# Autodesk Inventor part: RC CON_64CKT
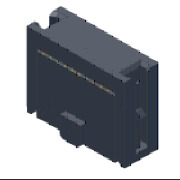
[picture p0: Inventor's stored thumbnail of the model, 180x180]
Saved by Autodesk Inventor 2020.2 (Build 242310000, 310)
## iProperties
Manager: www.cadconsulting.pl
Company: Fabian Stasiak CAD Consulting
IsCustomPart: 0
Created: 2014-02
Part Number: RC CON_64CKT
Material: Ogólny
Description: Podziałka 2.54mm (0.10cala), gniazdo, pionowe, dwurzędowe
Document SubType Name: Modeling
Designer: F.Stasiak
Language: pl-PL
Size Designation: Ribbon Cable Connector-13
Categories: <MemberInstance><Categories><Category DisplayName="Kable i wiązki przewodów" InternalName="e4a7e005-5e42-4d16-b293-125e7f0d0512" Mnemonic="CABLEANDHARNESS"><Cat
Density: 1 g/cm^3
Appearance: Dark Gray
Catalog Web Link: www.expertbooks.pl
Author: F.Stasiak
Subject: Zbiór ćwiczeń. Autodesk Inventor 2020. Kurs Professional
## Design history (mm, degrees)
sketch "Sketch1"
  geometry: L1 (41.27, -3)-(-41.27, -3); L2 (-40.52, -1.5)-(-40.52, -2.1); L3 (-41.27, -3)-(-41.27, -2.1); L4 (-40.52, -2.1)-(-41.27, -2.1); L5 (-41.27, -1.5)-(-40.52, -1.5); L6 (-41.27, -1.5)-(-41.27, 3); L7 (40.52, 1.5)-(40.52, 2.1); L8 (41.27, 1.5)-(41.27, -3); L9 (41.27, 1.5)-(40.52, 1.5); L10 (40.52, 2.1)-(41.27, 2.1); L11 (41.27, 3)-(41.27, 2.1); L12 (0, 3)-(0, -3); L13 (-41.27, 3)-(41.27, 3); 2 further points
  constraints: 26 end point, 8 parallel, 3 midpoint, 3 perpendicular, 2 horizontal, 1 coincident
  dimensions: "d0" = 82.54 distance of L1.start L1.end (derived); "d1" = 6 distance of L1.end L6.end; "d4" = 0.9 distance between parallel lines of L1 L4; "d5" = 0.75 distance of L2.end L3.end; "d6" = 0.6 distance of L2.start L2.end; "d8" = 0.75 distance of L7.end L10.end; "d9" = 0.6 distance of L7.start L7.end; "d10" = 6 distance of L1.start L11.start; "d12" = 0.9 distance of L11.start L10.end
extrude "Wyciągnięcie1" new body sketch "Sketch1" distance "d13" = 10.2; taper "d14" = 0 deg
sketch "Sketch2"
  geometry: L1 (0, 0)-(82.54, 0) reference; L2 (39.47, 3.6)-(43.07, 3.6); L3 (43.07, 3.6)-(43.07, 0.5); L4 (42.57, 0)-(39.97, 0); L5 (39.47, 0.5)-(39.47, 3.6); L6 (39.47, 0.5)-(39.97, 0); L7 (43.07, 0.5)-(42.57, 0); 1 further point
  constraints: 12 end point, 2 midpoint, 2 parallel, 1 horizontal, 1 perpendicular
  dimensions: "d15" = 3.6 distance of L2.start L2.end; "d17" = 0.5 horizontal distance of L4.end L5.start; "d19" = 135 deg angle of L6 L5; "d20" = 135 deg angle of L7 L3; "d21" = 0.5 horizontal distance of L4.start L3.end; "d22" = 3.6 distance between parallel lines of L1 L2
extrude "Wyciągnięcie2" join sketch "Sketch2" distance "d23" = 1; taper "d24" = 0 deg
sketch "Sketch3"
  geometry: L1 (-41.27, 3.6)-(-41.52, 3.6); L2 (-42.27, 2.1)-(-42.27, 1.22); L3 (-42.27, 1.22)-(-41.27, 1.22); L4 (-41.27, 1.22)-(-41.27, 3.6); L5 (41.27, 10.2)-(-41.27, 10.2) reference; L6 (0, 10.2)-(0, 0); L7 (-41.27, 0)-(41.27, 0) reference; L8 (-41.52, 3.6)-(-42.27, 2.1); L9 (41.27, 3.6)-(41.52, 3.6); L10 (42.27, 2.1)-(42.27, 1.22); L11 (42.27, 1.22)-(41.27, 1.22); L12 (41.27, 1.22)-(41.27, 3.6); L13 (41.52, 3.6)-(42.27, 2.1)
  constraints: 22 end point, 5 symmetric about line, 2 midpoint, 2 parallel, 2 perpendicular, 1 horizontal
  dimensions: "d25" = 82.54 diameter of L4 L6 (derived); "d26" = 1.22 distance between parallel lines of L3 L7; "d28" = 1 distance of L2.end L3.end; "d29" = 1.5 vertical distance of L1.end L2.start; "d30" = 0.88 distance of L2.start L2.end; "d31" = 0.25 distance of L1.start L1.end
extrude "Wyciągnięcie3" join sketch "Sketch3" stored distance "d32" = 1; taper "d33" = 0 deg
sketch "Sketch4"
  geometry: L1 (41.27, 3.6)-(41.52, 3.6) reference; L2 (41.27, 6.263)-(41.52, 6.263); L3 (42.27, 5.513)-(42.27, 5.263); L4 (42.27, 5.263)-(41.27, 5.263); L5 (41.27, 5.263)-(41.27, 6.263); L6 (-41.27, 10.2)-(41.27, 10.2) reference; L7 (41.27, 0)-(-41.27, 0) reference; L8 (0, 10.2)-(0, 0); L9 (41.52, 6.263)-(42.27, 5.513); L10 (-41.27, 5.263)-(-41.27, 6.263); L11 (-41.27, 6.263)-(-41.52, 6.263); L12 (-41.52, 6.263)-(-42.27, 5.513); L13 (-42.27, 5.513)-(-42.27, 5.263); L14 (-42.27, 5.263)-(-41.27, 5.263)
  constraints: 22 end point, 5 symmetric about line, 2 midpoint, 2 parallel, 1 horizontal, 1 perpendicular
  dimensions: "d34" = 1.663 distance between parallel lines of L4 L1; "d35" = 82.54 diameter of L5 L8 (derived); "d36" = 1 distance of L3.end L4.end; "d38" = 0.25 distance of L2.start L2.end; "d39" = 1 distance of L4.end L2.start; "d40" = 0.25 distance of L3.start L3.end
extrude "Wyciągnięcie4" join sketch "Sketch4" distance "d41" = 1; taper "d42" = 0 deg
sketch "Sketch5"
  geometry: L1 (41.52, -3.6)-(41.27, -3.6) reference; L2 (41.52, -6.263)-(41.27, -6.263); L3 (41.27, -6.263)-(41.27, -5.263); L4 (41.27, -5.263)-(42.27, -5.263); L5 (42.27, -5.263)-(42.27, -5.513); L6 (41.27, -10.2)-(-41.27, -10.2) reference; L7 (1.3, 0)-(-1.3, 0) reference; L8 (0, 0)-(0, -10.2); L9 (41.52, -6.263)-(42.27, -5.513); L10 (-41.27, -6.263)-(-41.27, -5.263); L11 (-41.52, -6.263)-(-41.27, -6.263); L12 (-41.52, -6.263)-(-42.27, -5.513); L13 (-42.27, -5.263)-(-42.27, -5.513); L14 (-41.27, -5.263)-(-42.27, -5.263)
  constraints: 22 end point, 5 symmetric about line, 2 midpoint, 2 parallel, 1 horizontal, 1 perpendicular
  dimensions: "d43" = 1.663 distance between parallel lines of L1 L4; "d44" = 82.54 diameter of L3 L8 (derived); "d45" = 1 distance of L2.end L3.end; "d46" = 1 distance of L3.end L4.end; "d47" = 0.25 distance of L2.start L2.end; "d48" = 0.25 distance of L4.end L5.end
extrude "Wyciągnięcie5" join sketch "Sketch5" distance "d49" = 1; taper "d50" = 0 deg
sketch "Sketch6"
  geometry: L1 (0, -10.2)-(39.97, -10.2) reference; L2 (-36.97, -6.736)-(-34.97, -10.2); L3 (-38.97, -10.2)-(-36.97, -6.736); L4 (-38.97, -10.2)-(-34.97, -10.2); L5 (0.5, -10.2)-(2.5, -6.736); L6 (2.5, -6.736)-(4.5, -10.2); L7 (0.5, -10.2)-(4.5, -10.2)
  constraints: 12 end point, 4 equal length, 2 point on line, 1 collinear
  dimensions: "d61" = 0.5 distance of L5.start L1.start; "d62" = 4 distance of L5.start L6.end
extrude "Wyciągnięcie6" cut sketch "Sketch6" distance "d63" = 0.1; taper "d64" = 0 deg
sketch "Sketch7"
  geometry: L1 (41.27, 3)-(41.27, -1.5) reference; L2 (38.995, 1.645)-(39.745, 1.645); L3 (39.745, 1.645)-(39.745, 0.895); L4 (39.745, 0.895)-(38.995, 0.895); L5 (38.995, 0.895)-(38.995, 1.645); L6 (38.995, -0.895)-(39.745, -0.895); L7 (39.745, -0.895)-(39.745, -1.645); L8 (39.745, -1.645)-(38.995, -1.645); L9 (38.995, -1.645)-(38.995, -0.895); L10 (39.37, 0.895)-(39.37, -0.895); 2 further points
  constraints: 18 end point, 7 equal length, 4 parallel, 3 midpoint, 3 perpendicular, 2 horizontal, 1 horizontal alignment
  dimensions: "d65" = 0.75 distance of L2.start L2.end; "d66" = 2.54 distance between parallel lines of L6 L2; "d67" = 1.525 distance between parallel lines of L1 L7
extrude "Wyciągnięcie7" cut sketch "Sketch7" distance "d68" = 3; taper "d69" = 0 deg
workplane "Work Plane1"
sketch "Sketch8"
  geometry: L1 (-42.251, -1.499)-(-41.4, -1.499); L2 (-42.955, -1.03)-(-42.251, -1.499); L3 (-42.955, -3.03)-(-42.955, -1.03); L4 (42.955, -3.03)-(-42.955, -3.03); L5 (-42.955, 3.03)-(42.955, 3.03); L6 (-41.4, -1.499)-(-41.4, 1.499); L7 (-41.27, 3)-(41.27, 3) reference; L8 (-41.27, -1.5)-(-41.27, 3) reference; L9 (-40.52, -1.5)-(-41.27, -1.5) reference; L10 (-40.52, -2.1)-(-40.52, -1.5) reference; L11 (-41.27, -2.1)-(-40.52, -2.1) reference; L12 (-41.27, -3)-(-41.27, -2.1) reference; L13 (41.27, -3)-(-41.27, -3) reference; L14 (41.27, 1.5)-(41.27, -3) reference; L15 (40.52, 1.5)-(41.27, 1.5) reference; L16 (40.52, 2.1)-(40.52, 1.5) reference; L17 (41.27, 2.1)-(40.52, 2.1) reference; L18 (41.27, 3)-(41.27, 2.1) reference; L19 (0, 3)-(0, -3); L20 (-41.4, 0)-(-42.954, 0); L21 (-42.955, 1.03)-(-42.251, 1.499); L22 (-42.955, 3.03)-(-42.955, 1.03); L23 (-42.251, 1.499)-(-41.4, 1.499); L24 (42.955, 3.03)-(42.955, 1.03); L25 (42.955, 1.03)-(42.251, 1.499); L26 (42.251, 1.499)-(41.4, 1.499); L27 (41.4, -1.499)-(41.4, 1.499); L28 (42.251, -1.499)-(41.4, -1.499); L29 (42.955, -1.03)-(42.251, -1.499); L30 (42.955, -3.03)-(42.955, -1.03); 4 further points
  constraints: 36 end point, 8 symmetric about line, 5 midpoint, 4 perpendicular, 3 parallel, 1 coincident, 1 horizontal, 1 horizontal alignment
  dimensions: "d160" = 2 distance of L3.start L2.start; "d161" = 0.85079 distance of L1.start L1.end; "d162" = 2.99894 distance of L1.end L6.end; "d163" = 56.3099 deg angle of L3 L2; "d164" = 0.13 distance between parallel lines of L8 L6; "d165" = 85.91 distance of L5.start L5.end (derived)
extrude "Wyciągnięcie8" join sketch "Sketch8" distance "d90" = 2.5; taper "d91" = 0 deg
sketch "Sketch10"
  geometry: L1 (-42.955, 3.03)-(-42.955, 1.03) reference; L2 (42.955, 3.03)-(-42.955, 3.03) reference; L3 (42.955, 1.03)-(42.955, 3.03) reference; L4 (42.251, 1.499)-(42.955, 1.03) reference; L5 (41.4, 1.499)-(42.251, 1.499) reference; L6 (41.4, -1.499)-(41.4, 1.499) reference; L7 (42.251, -1.499)-(41.4, -1.499) reference; L8 (42.955, -1.03)-(42.251, -1.499) reference; L9 (42.955, -3.03)-(42.955, -1.03) reference; L10 (-42.955, -3.03)-(42.955, -3.03) reference; L11 (-42.955, -1.03)-(-42.955, -3.03) reference; L12 (-42.251, -1.499)-(-42.955, -1.03) reference; L13 (-41.4, -1.499)-(-42.251, -1.499) reference; L14 (-41.4, 1.499)-(-41.4, -1.499) reference; L15 (-42.251, 1.499)-(-41.4, 1.499) reference; L16 (-42.955, 1.03)-(-42.251, 1.499) reference; L17 (41.27, -1.5)-(40.52, -1.5) reference; L18 (40.52, -1.5)-(40.52, -2.1) reference; L19 (40.52, -2.1)-(41.27, -2.1) reference; L20 (-41.27, 1.5)-(-40.52, 1.5) reference; L21 (-40.52, 1.5)-(-40.52, 2.1) reference; L22 (-40.52, 2.1)-(-41.27, 2.1) reference; L23 (-41.28, 1.51)-(-40.53, 1.51); L24 (-40.53, 1.51)-(-40.53, 2.09); L25 (-40.53, 2.09)-(-41.28, 2.09); L26 (-41.28, 2.09)-(-41.28, 3.03); L27 (41.28, -2.09)-(40.53, -2.09); L28 (40.53, -2.09)-(40.53, -1.51); L29 (40.53, -1.51)-(41.28, -1.51); L30 (41.28, -3.03)-(41.28, -2.09); L31 (-41.4, -1.499)-(-41.28, -1.499); L32 (-41.4, 1.499)-(-41.28, 1.499); L33 (-41.28, -3.03)-(-41.28, -1.499); L34 (-41.28, 1.499)-(-41.28, 1.51); L35 (41.4, 1.499)-(41.28, 1.499); L36 (41.4, -1.499)-(41.28, -1.499); L37 (41.28, -1.51)-(41.28, -1.499); L38 (41.28, 1.499)-(41.28, 3.03); 4 further points
  constraints: 32 end point, 8 perpendicular, 7 parallel, 4 midpoint, 4 point on line, 2 horizontal, 2 horizontal alignment
  dimensions: "d167" = 0.01 distance between parallel lines of L20 L23; "d168" = 0.01 distance between parallel lines of L21 L24; "d170" = 0.01 distance from line of L26 L22.end; "d172" = 0.01 distance between parallel lines of L19 L27; "d173" = 0.01 distance between parallel lines of L18 L28; "d174" = 0.01 distance from line of L30 L19.end; "d180" = 0.01 distance from line of L20.start L34; "d181" = 0.12 distance of L13.start L31.end; "d182" = 0.01 distance of L36.end L17.start; "d183" = 0.12 distance of L5.start L35.end
extrude "Wyciągnięcie9" join sketch "Sketch10" distance "d157" = 10.7; taper "d158" = 0 deg
sketch "Sketch12"
  geometry: L1 (42.955, 13.2)-(-42.955, 13.2) reference; L2 (0, 13.2)-(0, 4.865); L3 (-42.955, 13.2)-(-42.955, 0) reference; L4 (-42.955, 0)-(-41.28, 0); L5 (-41.28, 0)-(-41.28, 1.21); L6 (-41.28, 1.21)-(-42.955, 1.21); L7 (-42.955, 1.21)-(-42.955, 0); L8 (-41.52, 3.6)-(-41.27, 3.6) reference; L9 (-42.27, 2.1)-(-41.52, 3.6) reference; L10 (-42.27, 1.22)-(-42.27, 2.1) reference; L11 (-41.27, 1.22)-(-42.27, 1.22) reference; L12 (41.28, 0)-(41.28, 1.21); L13 (41.28, 1.21)-(42.955, 1.21); L14 (42.955, 1.21)-(42.955, 0); L15 (42.955, 0)-(41.28, 0); L16 (-41.27, 3.6)-(-41.27, 1.22) reference
  constraints: 18 end point, 4 symmetric about line, 2 parallel, 2 perpendicular, 1 horizontal, 1 midpoint
  dimensions: "d177" = 0.01 distance between parallel lines of L11 L6; "d243" = 1.675 distance of L3.end L4.end
extrude "Wyciągnięcie10" join sketch "Sketch12" stored distance "d178" = 6.06; taper "d179" = 0 deg
sketch "Sketch20" dims "d253" = 10
  geometry: L1 (85.91, -2.49)-(0, -2.49) reference; L2 (85.91, 0)-(85.91, -2.49) reference; L3 (85.91, 0)-(0, 0) reference; L4 (0, 0)-(0, -2.49) reference; L5 (84.225, -3)-(1.685, -3) reference; 68 further points
  constraints: 2 midpoint, 2 vertical alignment, 1 horizontal, 63 other
  dimensions: "d240" = 0.25 distance from line of L5 point (2.95, -2.75); "d241" = 0.25 distance from line of L5 point (42.955, -2.75); "d242" = 0.25 distance from line of L3 point (42.955, 0.25); "d247" = 40.005 distance of point (42.955, -2.75) point (2.95, -2.75) (derived); "d250" = 1.27 distance of point (2.95, -2.75) point (4.22, -2.75)
sketch "Sketch21"
  geometry: L1 (0, 2.49)-(85.91, 2.49) reference; L2 (0, 2.49)-(0, 0) reference; L3 (0, 0)-(85.91, 0) reference; L4 (85.91, 0)-(85.91, 2.49) reference; 2 further points
workpoint "Work Point1"
workpoint "Work Point2"
node "1"
node "2"
node "3"
node "4"
node "5"
node "6"
node "7"
node "8"
node "9"
node "10"
node "11"
node "12"
node "13"
node "14"
node "15"
node "16"
node "17"
node "18"
node "19"
node "20"
node "21"
node "22"
node "23"
node "24"
node "25"
node "26"
node "27"
node "28"
node "29"
node "30"
node "31"
node "32"
node "33"
node "34"
node "35"
node "36"
node "37"
node "38"
node "39"
node "40"
node "41"
node "42"
node "43"
node "44"
node "45"
node "46"
node "47"
node "48"
node "49"
node "50"
node "51"
node "52"
node "53"
node "54"
node "55"
node "56"
node "57"
node "58"
node "59"
node "60"
node "61"
node "62"
node "63"
node "64"
body "Solid1"
chamfer "Faza1" distance "d70" = 0.5; stored, may be unused: second distance "d71" = 2, angle "d72" = 45 deg
pattern_linear "Wzór prostokątny1" dims "d75" = 2.54
chamfer "Faza2" distance "d185" = 1; stored, may be unused: second distance "d186" = 2, angle "d187" = 45 deg
chamfer "Faza3" distance "d188" = 1.749; stored, may be unused: second distance "d189" = 2, angle "d190" = 45 deg
chamfer "Faza4" distance "d191" = 10.71; stored, may be unused: second distance "d192" = 0.03, angle "d193" = 45 deg
chamfer "Faza5" distance "d194" = 10.71; stored, may be unused: second distance "d195" = 0.03, angle "d196" = 45 deg
chamfer "Faza8" distance "d203" = 0.5; stored, may be unused: second distance "d204" = 0.03, angle "d205" = 45 deg
node "Projected Loop2"
node "Projected Loop3"
node "Projected Loop4"
other parameters: "DimA" = 82.54 [user parameter], "DimB" = 85.91 [user parameter], "DimC" = 40.005 [user parameter], "d123" = 0.01, "d126" = 0.01, "d148" = 0.01, "d152" = 0.01, "d166" = 0.01, "d169" = 0.01, "d171" = 0.01, "d175" = 0.01, "d234" = 10.7
